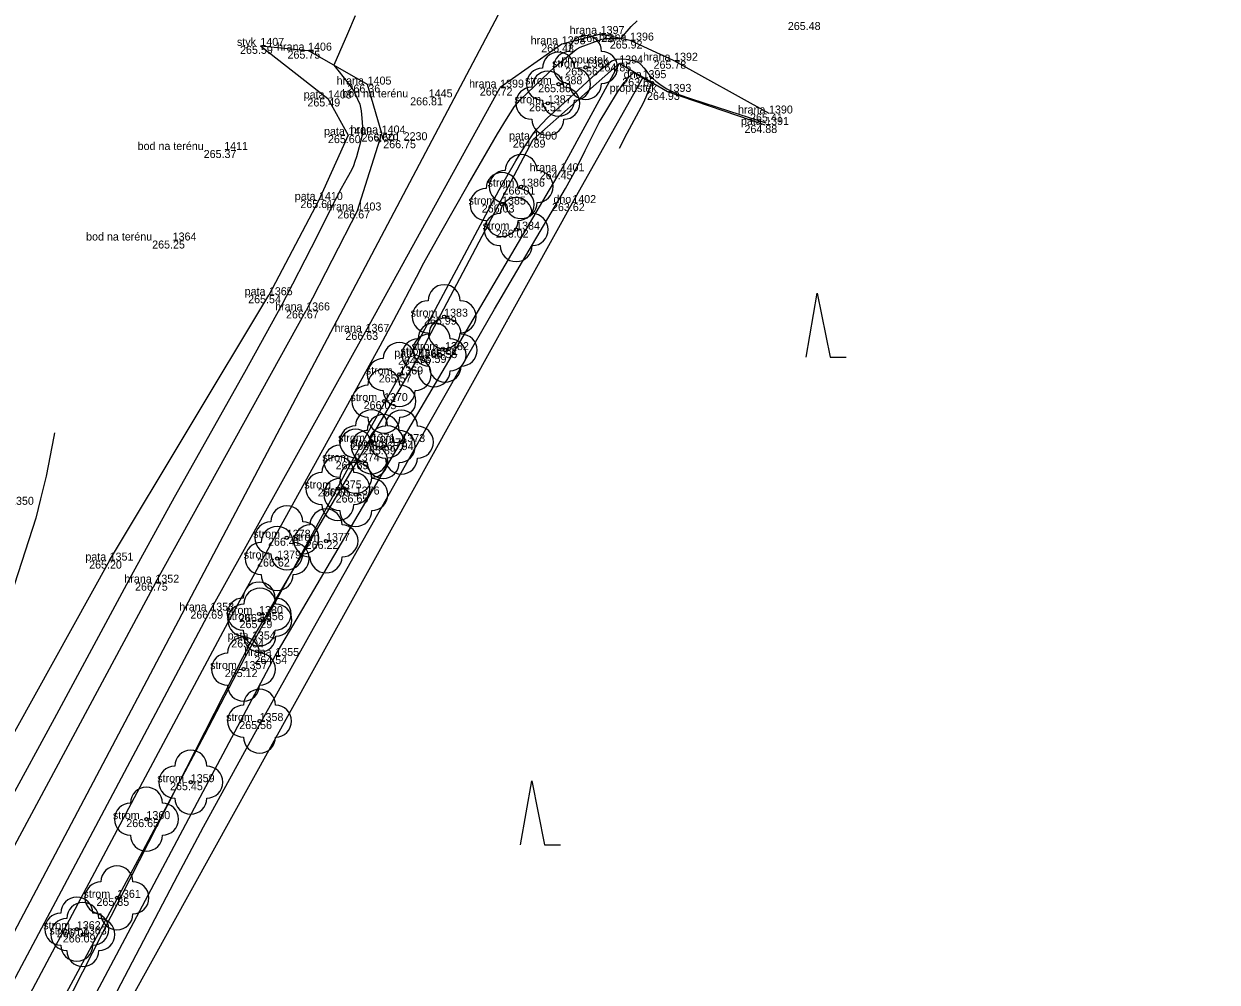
# Model space of a CAD drawing. Extents: x -567962 to -566460, y -1093720 to -1089838.
# Drawn here: x -567164.4 to -567089.8, y -1090846.6 to -1090786.7 of the extents above; entities that cross this region are included whole.
import ezdxf

# ---------------------------------------------------------------- set-up
doc = ezdxf.new("R2010")
doc.units = 0
for name, color, linetype in [('0_osa hráze', 7, 'Continuous'), ('bod_znacka', 7, 'Continuous'), ('cislo_bodu', 7, 'Continuous'), ('hlavni_vrst', 7, 'Continuous'), ('hrana_L', 7, 'Continuous'), ('hrana_P', 7, 'Continuous'), ('kod_bodu', 7, 'Continuous'), ('norm_vrst', 7, 'Continuous'), ('ostatni', 7, 'Continuous'), ('propustky', 7, 'Continuous'), ('stromy', 7, 'Continuous'), ('Vrstva 1', 7, 'Continuous'), ('vyska_bodu', 7, 'Continuous')]:
    doc.layers.add(name, color=color, linetype=linetype)

# ---------------------------------------------------------------- blocks, each defined once
blk = doc.blocks.new('3.08')
at = {"layer": 'Vrstva 1'}
blk.add_lwpolyline([(-0.07, 0), (0, 0.4), (0.08, 0), (0.18, 0)], dxfattribs=at)

msp = doc.modelspace()

# ---------------------------------------------------------------- linework, layer by layer
at = {"layer": '0_osa hráze'}
msp.add_lwpolyline([(-567089.84, -1090700.38), (-567096.414, -1090713.39), (-567177.884, -1090867.779)], dxfattribs=at)
at = {"layer": 'bod_znacka'}
for p, q in [((-567128.36, -1090787.29), (-567128.36, -1090787.29)), ((-567149.62, -1090788.03), (-567149.62, -1090788.03)), ((-567130.79, -1090787.93), (-567130.79, -1090787.93)), ((-567126.52, -1090787.7), (-567126.52, -1090787.7)), ((-567146.64, -1090788.33), (-567146.64, -1090788.33)), ((-567123.77, -1090788.96), (-567123.77, -1090788.96)), ((-567129.3, -1090789.38), (-567129.3, -1090789.38)), ((-567127.2, -1090789.13), (-567127.2, -1090789.13)), ((-567142.92, -1090790.45), (-567142.92, -1090790.45)), ((-567130.99, -1090790.43), (-567130.99, -1090790.43)), ((-567125.74, -1090790.05), (-567125.74, -1090790.05)), ((-567134.64, -1090790.64), (-567134.64, -1090790.64)), ((-567124.18, -1090790.91), (-567124.18, -1090790.91)), ((-567145.4, -1090791.32), (-567145.4, -1090791.32)), ((-567139.1, -1090791.25), (-567139.1, -1090791.25)), ((-567131.66, -1090791.62), (-567131.66, -1090791.62)), ((-567117.84, -1090792.26), (-567117.84, -1090792.26)), ((-567118.08, -1090792.98), (-567118.08, -1090792.98)), ((-567144.13, -1090793.61), (-567144.13, -1090793.61)), ((-567142.04, -1090793.51), (-567142.04, -1090793.51)), ((-567140.67, -1090793.93), (-567140.67, -1090793.93)), ((-567132.57, -1090793.89), (-567132.57, -1090793.89)), ((-567151.88, -1090794.54), (-567151.88, -1090794.54)), ((-567130.86, -1090795.87), (-567130.86, -1090795.87)), ((-567133.33, -1090796.83), (-567133.33, -1090796.83)), ((-567145.96, -1090797.67), (-567145.96, -1090797.67)), ((-567130.13, -1090797.86), (-567130.13, -1090797.86)), ((-567143.55, -1090798.32), (-567143.55, -1090798.32)), ((-567134.52, -1090797.95), (-567134.52, -1090797.95)), ((-567133.64, -1090799.52), (-567133.64, -1090799.52)), ((-567155.1, -1090800.2), (-567155.1, -1090800.2)), ((-567149.09, -1090803.62), (-567149.09, -1090803.62)), ((-567146.76, -1090804.57), (-567146.76, -1090804.57)), ((-567138.14, -1090804.96), (-567138.14, -1090804.96)), ((-567143.05, -1090805.91), (-567143.05, -1090805.91)), ((-567139.74, -1090807.47), (-567139.74, -1090807.47)), ((-567138.77, -1090807.35), (-567138.77, -1090807.35)), ((-567138.08, -1090807.05), (-567138.08, -1090807.05)), ((-567140.94, -1090808.57), (-567140.94, -1090808.57)), ((-567141.9, -1090810.24), (-567141.9, -1090810.24)), ((-567142.67, -1090812.78), (-567142.67, -1090812.78)), ((-567140.81, -1090812.8), (-567140.81, -1090812.8)), ((-567141.94, -1090813.07), (-567141.94, -1090813.07)), ((-567143.66, -1090814), (-567143.66, -1090814)), ((-567144.78, -1090815.7), (-567144.78, -1090815.7)), ((-567143.66, -1090816.08), (-567143.66, -1090816.08)), ((-567147.97, -1090818.78), (-567147.97, -1090818.78)), ((-567145.52, -1090818.98), (-567145.52, -1090818.98)), ((-567159.04, -1090820.21), (-567159.04, -1090820.21)), ((-567148.57, -1090820.08), (-567148.57, -1090820.08)), ((-567156.18, -1090821.59), (-567156.18, -1090821.59)), ((-567152.75, -1090823.34), (-567152.75, -1090823.34)), ((-567149.7, -1090823.55), (-567149.7, -1090823.55)), ((-567149.65, -1090823.93), (-567149.65, -1090823.93)), ((-567150.15, -1090825.14), (-567150.15, -1090825.14)), ((-567148.69, -1090826.17), (-567148.69, -1090826.17)), ((-567150.67, -1090826.99), (-567150.67, -1090826.99)), ((-567149.67, -1090830.24), (-567149.67, -1090830.24)), ((-567153.97, -1090834.06), (-567153.97, -1090834.06)), ((-567156.74, -1090836.37), (-567156.74, -1090836.37)), ((-567158.58, -1090841.29), (-567158.58, -1090841.29)), ((-567161.09, -1090843.25), (-567161.09, -1090843.25)), ((-567160.71, -1090843.58), (-567160.71, -1090843.58))]:
    msp.add_line(p, q, dxfattribs=at)
at = {"layer": 'hlavni_vrst'}
for points in [[(-567162.873, -1090849.36), (-567157.121, -1090838.678), (-567155.184, -1090835.033), (-567153.089, -1090831.079), (-567150.566, -1090826.245), (-567149.768, -1090824.77), (-567149.142, -1090823.648), (-567147.639, -1090820.878), (-567143.703, -1090813.646), (-567141.369, -1090809.457), (-567140.176, -1090807.295), (-567134.692, -1090797.023), (-567133.662, -1090795.222), (-567133.119, -1090794.348), (-567132.54, -1090793.478), (-567132.329, -1090793.217), (-567131.68, -1090792.532), (-567130.011, -1090791.036), (-567128.681, -1090789.807), (-567128.344, -1090789.503), (-567127.655, -1090788.976), (-567127.346, -1090788.873), (-567127.122, -1090788.845), (-567126.964, -1090788.845), (-567126.761, -1090788.859), (-567126.552, -1090788.894), (-567126.363, -1090788.938), (-567126.14, -1090789.014), (-567125.963, -1090789.098), (-567125.829, -1090789.212), (-567125.656, -1090789.396), (-567125.535, -1090789.552), (-567125.459, -1090789.669), (-567125.323, -1090789.845), (-567125.103, -1090790.068), (-567124.912, -1090790.238), (-567124.579, -1090790.487), (-567124.216, -1090790.718), (-567123.842, -1090790.904), (-567123.464, -1090791.071), (-567122.745, -1090791.326), (-567120.306, -1090792.117), (-567118.032, -1090792.837)], [(-567162.493, -1090812.221), (-567162.528, -1090812.45), (-567163.012, -1090814.932), (-567163.353, -1090816.337), (-567163.66, -1090817.553), (-567164.977, -1090821.675), (-567165.662, -1090823.624), (-567166.58, -1090826.191), (-567167.297, -1090828.123), (-567168.37, -1090830.969), (-567169.425, -1090833.739), (-567170.866, -1090837.606), (-567171.566, -1090839.547), (-567172.449, -1090842.05), (-567173.114, -1090844.011), (-567173.801, -1090846.164), (-567174.216, -1090847.494)]]:
    msp.add_lwpolyline(points, dxfattribs=at)
at = {"layer": 'hrana_L'}
for p, q in [((-567128.36, -1090787.29), (-567130.79, -1090787.93)), ((-567126.52, -1090787.7), (-567128.36, -1090787.29)), ((-567149.62, -1090788.03), (-567146.64, -1090788.33)), ((-567149.62, -1090788.03), (-567145.4, -1090791.32)), ((-567130.79, -1090787.93), (-567134.64, -1090790.64)), ((-567123.77, -1090788.96), (-567126.52, -1090787.7)), ((-567142.92, -1090790.45), (-567146.64, -1090788.33)), ((-567117.84, -1090792.26), (-567123.77, -1090788.96)), ((-567127.2, -1090789.13), (-567132.57, -1090793.89)), ((-567127.2, -1090789.13), (-567130.86, -1090795.87)), ((-567142.04, -1090793.51), (-567142.92, -1090790.45)), ((-567143.05, -1090805.91), (-567134.64, -1090790.64)), ((-567118.08, -1090792.98), (-567124.18, -1090790.91)), ((-567145.4, -1090791.32), (-567144.13, -1090793.61)), ((-567144.13, -1090793.61), (-567145.96, -1090797.67)), ((-567143.55, -1090798.32), (-567142.04, -1090793.51)), ((-567139.74, -1090807.47), (-567132.57, -1090793.89)), ((-567148.69, -1090826.17), (-567130.86, -1090795.87)), ((-567145.96, -1090797.67), (-567149.09, -1090803.62)), ((-567143.55, -1090798.32), (-567146.76, -1090804.57)), ((-567159.04, -1090820.21), (-567149.09, -1090803.62)), ((-567156.18, -1090821.59), (-567146.76, -1090804.57)), ((-567152.75, -1090823.34), (-567143.05, -1090805.91)), ((-567139.74, -1090807.47), (-567150.15, -1090825.14)), ((-567159.04, -1090820.21), (-567174.87, -1090848.67)), ((-567156.18, -1090821.59), (-567171.65, -1090850.41)), ((-567168.28, -1090852.53), (-567152.75, -1090823.34)), ((-567150.15, -1090825.14), (-567164.27, -1090852.89)), ((-567161.26, -1090849.83), (-567148.69, -1090826.17))]:
    msp.add_line(p, q, dxfattribs=at)
at = {"layer": 'hrana_P'}
for p, q in [((-567125.74, -1090790.05), (-567130.13, -1090797.86)), ((-567130.13, -1090797.86), (-567157.68, -1090847.55))]:
    msp.add_line(p, q, dxfattribs=at)
at = {"layer": 'norm_vrst'}
for points in [[(-567166.68, -1090852.281), (-567156.973, -1090834.031), (-567151.464, -1090823.75), (-567148.069, -1090817.56), (-567142.129, -1090806.774), (-567141.629, -1090805.847), (-567140.741, -1090804.164), (-567139.869, -1090802.486), (-567139.399, -1090801.596), (-567138.35, -1090799.698), (-567136.631, -1090796.701), (-567134.795, -1090793.532), (-567134.247, -1090792.613), (-567133.746, -1090791.815), (-567133.382, -1090791.403), (-567131.603, -1090789.698), (-567131.235, -1090789.367), (-567129.883, -1090788.262), (-567129.821, -1090788.221), (-567129.631, -1090788.122), (-567128.281, -1090787.61), (-567128.104, -1090787.568), (-567127.886, -1090787.562), (-567127.097, -1090787.571), (-567126.449, -1090786.829), (-567126.08, -1090786.461)], [(-567143.707, -1090786.163), (-567144.168, -1090787.289), (-567144.667, -1090788.435), (-567145.036, -1090789.244), (-567144.132, -1090790.365), (-567143.855, -1090790.747), (-567143.763, -1090790.915), (-567143.546, -1090791.363), (-567143.416, -1090791.684), (-567143.331, -1090792.091), (-567143.279, -1090792.55), (-567143.241, -1090793.092), (-567143.25, -1090793.437), (-567143.286, -1090793.695), (-567143.442, -1090794.346), (-567143.617, -1090794.962), (-567143.713, -1090795.263), (-567143.811, -1090795.531), (-567143.933, -1090795.809), (-567144.19, -1090796.28), (-567144.573, -1090796.941), (-567144.866, -1090797.5), (-567146.445, -1090800.665), (-567148, -1090803.695), (-567148.276, -1090804.217), (-567150.622, -1090808.44), (-567155.002, -1090816.274), (-567157.691, -1090821.164), (-567162.51, -1090830.095), (-567165.357, -1090835.349)], [(-567164.006, -1090857.513), (-567154.773, -1090839.877), (-567153.164, -1090836.85), (-567149.769, -1090830.667), (-567146.294, -1090824.435), (-567139.179, -1090811.796), (-567137.063, -1090808.071), (-567134.998, -1090804.501), (-567132.83, -1090800.797), (-567130.548, -1090796.938), (-567130, -1090795.922), (-567129.32, -1090794.575), (-567128.876, -1090793.655), (-567128.444, -1090792.817), (-567127.919, -1090791.917), (-567127.303, -1090790.932), (-567127.042, -1090790.532), (-567126.894, -1090790.327), (-567126.58, -1090789.959), (-567126.277, -1090789.706), (-567125.312, -1090790.273), (-567125.188, -1090790.353), (-567125.195, -1090790.399), (-567125.533, -1090791.238), (-567125.706, -1090791.608), (-567126.722, -1090793.503), (-567127.209, -1090794.449)]]:
    msp.add_lwpolyline(points, dxfattribs=at)
at = {"layer": 'propustky'}
msp.add_line((-567124.18, -1090790.91), (-567127.2, -1090789.13), dxfattribs=at)
at = {"layer": 'stromy'}
for centre in [(-567129.3, -1090789.38), (-567130.99, -1090790.43), (-567131.66, -1090791.62), (-567133.33, -1090796.83), (-567134.52, -1090797.95), (-567133.64, -1090799.52), (-567138.14, -1090804.96), (-567138.77, -1090807.35), (-567138.08, -1090807.05), (-567140.94, -1090808.57), (-567141.9, -1090810.24), (-567142.67, -1090812.78), (-567140.81, -1090812.8), (-567141.94, -1090813.07), (-567143.66, -1090814), (-567144.78, -1090815.7), (-567143.66, -1090816.08), (-567147.97, -1090818.78), (-567145.52, -1090818.98), (-567148.57, -1090820.08), (-567149.7, -1090823.55), (-567149.65, -1090823.93), (-567150.67, -1090826.99), (-567149.67, -1090830.24), (-567153.97, -1090834.06), (-567156.74, -1090836.37), (-567158.58, -1090841.29), (-567161.09, -1090843.25), (-567160.71, -1090843.58)]:
    msp.add_circle(centre, 0.1, dxfattribs=at)
for centre, start, end in [((-567129.3, -1090788.38), 0, 180), ((-567130.99, -1090789.43), 0, 180), ((-567130.3, -1090789.38), 90, 270), ((-567128.3, -1090789.38), 270, 90), ((-567131.99, -1090790.43), 90, 270), ((-567131.66, -1090790.62), 0, 180), ((-567129.99, -1090790.43), 270, 90), ((-567129.3, -1090790.38), 180, 0), ((-567132.66, -1090791.62), 90, 270), ((-567130.66, -1090791.62), 270, 90), ((-567130.99, -1090791.43), 180, 0), ((-567131.66, -1090792.62), 180, 0), ((-567133.33, -1090795.83), 0, 180), ((-567134.52, -1090796.95), 0, 180), ((-567134.33, -1090796.83), 90, 270), ((-567132.33, -1090796.83), 270, 90), ((-567135.52, -1090797.95), 90, 270), ((-567133.52, -1090797.95), 270, 90), ((-567133.64, -1090798.52), 0, 180), ((-567133.33, -1090797.83), 180, 0), ((-567134.64, -1090799.52), 90, 270), ((-567132.64, -1090799.52), 270, 90), ((-567134.52, -1090798.95), 180, 0), ((-567133.64, -1090800.52), 180, 0), ((-567138.14, -1090803.96), 0, 180), ((-567139.14, -1090804.96), 90, 270), ((-567137.14, -1090804.96), 270, 90), ((-567138.77, -1090806.35), 0, 180), ((-567138.08, -1090806.05), 0, 180), ((-567139.08, -1090807.05), 90, 270), ((-567138.14, -1090805.96), 180, 0), ((-567137.08, -1090807.05), 270, 90), ((-567140.94, -1090807.57), 0, 180), ((-567139.77, -1090807.35), 90, 270), ((-567137.77, -1090807.35), 270, 90), ((-567141.94, -1090808.57), 90, 270), ((-567139.94, -1090808.57), 270, 90), ((-567141.9, -1090809.24), 0, 180), ((-567138.77, -1090808.35), 180, 0), ((-567138.08, -1090808.05), 180, 0), ((-567142.9, -1090810.24), 90, 270), ((-567140.94, -1090809.57), 180, 0), ((-567140.9, -1090810.24), 270, 90), ((-567142.67, -1090811.78), 0, 180), ((-567141.94, -1090812.07), 0, 180), ((-567141.9, -1090811.24), 180, 0), ((-567140.81, -1090811.8), 0, 180), ((-567143.67, -1090812.78), 90, 270), ((-567143.66, -1090813), 0, 180), ((-567142.94, -1090813.07), 90, 270), ((-567141.81, -1090812.8), 90, 270), ((-567141.67, -1090812.78), 270, 90), ((-567140.94, -1090813.07), 270, 90), ((-567139.81, -1090812.8), 270, 90), ((-567144.66, -1090814), 90, 270), ((-567142.66, -1090814), 270, 90), ((-567144.78, -1090814.7), 0, 180), ((-567143.66, -1090815.08), 0, 180), ((-567142.67, -1090813.78), 180, 0), ((-567141.94, -1090814.07), 180, 0), ((-567140.81, -1090813.8), 180, 0), ((-567145.78, -1090815.7), 90, 270), ((-567143.66, -1090815), 180, 0), ((-567143.78, -1090815.7), 270, 90), ((-567144.66, -1090816.08), 90, 270), ((-567142.66, -1090816.08), 270, 90), ((-567147.97, -1090817.78), 0, 180), ((-567145.52, -1090817.98), 0, 180), ((-567144.78, -1090816.7), 180, 0), ((-567143.66, -1090817.08), 180, 0), ((-567148.97, -1090818.78), 90, 270), ((-567146.52, -1090818.98), 90, 270), ((-567146.97, -1090818.78), 270, 90), ((-567144.52, -1090818.98), 270, 90), ((-567148.57, -1090819.08), 0, 180), ((-567149.57, -1090820.08), 90, 270), ((-567147.57, -1090820.08), 270, 90), ((-567147.97, -1090819.78), 180, 0), ((-567145.52, -1090819.98), 180, 0), ((-567149.7, -1090822.55), 0, 180), ((-567148.57, -1090821.08), 180, 0), ((-567149.65, -1090822.93), 0, 180), ((-567150.7, -1090823.55), 90, 270), ((-567150.65, -1090823.93), 90, 270), ((-567148.7, -1090823.55), 270, 90), ((-567148.65, -1090823.93), 270, 90), ((-567149.7, -1090824.55), 180, 0), ((-567150.67, -1090825.99), 0, 180), ((-567149.65, -1090824.93), 180, 0), ((-567151.67, -1090826.99), 90, 270), ((-567149.67, -1090826.99), 270, 90), ((-567150.67, -1090827.99), 180, 0), ((-567149.67, -1090829.24), 0, 180), ((-567150.67, -1090830.24), 90, 270), ((-567148.67, -1090830.24), 270, 90), ((-567149.67, -1090831.24), 180, 0), ((-567153.97, -1090833.06), 0, 180), ((-567154.97, -1090834.06), 90, 270), ((-567152.97, -1090834.06), 270, 90), ((-567156.74, -1090835.37), 0, 180), ((-567153.97, -1090835.06), 180, 0), ((-567157.74, -1090836.37), 90, 270), ((-567155.74, -1090836.37), 270, 90), ((-567156.74, -1090837.37), 180, 0), ((-567158.58, -1090840.29), 0, 180), ((-567159.58, -1090841.29), 90, 270), ((-567157.58, -1090841.29), 270, 90), ((-567161.09, -1090842.25), 0, 180), ((-567160.71, -1090842.58), 0, 180), ((-567162.09, -1090843.25), 90, 270), ((-567161.71, -1090843.58), 90, 270), ((-567160.09, -1090843.25), 270, 90), ((-567159.71, -1090843.58), 270, 90), ((-567158.58, -1090842.29), 180, 0), ((-567161.09, -1090844.25), 180, 0), ((-567160.71, -1090844.58), 180, 0)]:
    msp.add_arc(centre, 1, start, end, dxfattribs=at)

# ---------------------------------------------------------------- block references
at = {"layer": 'ostatni', "xscale": 10, "yscale": 10}
for p in [(-567114.822, -1090807.496), (-567132.668, -1090837.974)]:
    msp.add_blockref('3.08', p, dxfattribs=at)

# ---------------------------------------------------------------- texts
at = {"layer": 'cislo_bodu'}
for s, p in [('1398', (-567130.79, -1090787.93)), ('1397', (-567128.36, -1090787.29)), ('1396', (-567126.52, -1090787.7)), ('1407', (-567149.62, -1090788.03)), ('1406', (-567146.64, -1090788.33)), ('1389', (-567129.3, -1090789.38)), ('1394', (-567127.2, -1090789.13)), ('1392', (-567123.77, -1090788.96)), ('1395', (-567125.74, -1090790.05)), ('1405', (-567142.92, -1090790.45)), ('1399', (-567134.64, -1090790.64)), ('1388', (-567130.99, -1090790.43)), ('1393', (-567124.18, -1090790.91)), ('1408', (-567145.4, -1090791.32)), ('1445', (-567139.1, -1090791.25)), ('1387', (-567131.66, -1090791.62)), ('1390', (-567117.84, -1090792.26)), ('1391', (-567118.08, -1090792.98)), ('1409', (-567144.13, -1090793.61)), ('1404', (-567142.04, -1090793.51)), ('2230', (-567140.67, -1090793.93)), ('1400', (-567132.57, -1090793.89)), ('1411', (-567151.88, -1090794.54)), ('1401', (-567130.86, -1090795.87)), ('1386', (-567133.33, -1090796.83)), ('1410', (-567145.96, -1090797.67)), ('1403', (-567143.55, -1090798.32)), ('1385', (-567134.52, -1090797.95)), ('1402', (-567130.13, -1090797.86)), ('1384', (-567133.64, -1090799.52)), ('1364', (-567155.1, -1090800.2)), ('1365', (-567149.09, -1090803.62)), ('1366', (-567146.76, -1090804.57)), ('1383', (-567138.14, -1090804.96)), ('1367', (-567143.05, -1090805.91)), ('1381', (-567138.77, -1090807.35)), ('1382', (-567138.08, -1090807.05)), ('1368', (-567139.74, -1090807.47)), ('1369', (-567140.94, -1090808.57)), ('1370', (-567141.9, -1090810.24)), ('1371', (-567142.67, -1090812.78)), ('1372', (-567141.94, -1090813.07)), ('1373', (-567140.81, -1090812.8)), ('1374', (-567143.66, -1090814)), ('1375', (-567144.78, -1090815.7)), ('1376', (-567143.66, -1090816.08)), ('1350', (-567165.26, -1090816.72)), ('1378', (-567147.97, -1090818.78)), ('1377', (-567145.52, -1090818.98)), ('1351', (-567159.04, -1090820.21)), ('1379', (-567148.57, -1090820.08)), ('1352', (-567156.18, -1090821.59)), ('1353', (-567152.75, -1090823.34)), ('1380', (-567149.7, -1090823.55)), ('1356', (-567149.65, -1090823.93)), ('1354', (-567150.15, -1090825.14)), ('1355', (-567148.69, -1090826.17)), ('1357', (-567150.67, -1090826.99)), ('1358', (-567149.67, -1090830.24)), ('1359', (-567153.97, -1090834.06)), ('1360', (-567156.74, -1090836.37)), ('1361', (-567158.58, -1090841.29)), ('1362', (-567161.09, -1090843.25)), ('1363', (-567160.71, -1090843.58))]:
    msp.add_text(s, height=0.5, dxfattribs=at).set_placement(p)
at = {"layer": 'kod_bodu'}
for s, p in [('hrana', (-567132.727, -1090787.93)), ('hrana', (-567130.297, -1090787.29)), ('hrana', (-567128.457, -1090787.7)), ('styk', (-567151.084, -1090788.03)), ('hrana', (-567148.577, -1090788.33)), ('strom', (-567131.394, -1090789.38)), ('propustek', (-567130.814, -1090789.13)), ('hrana', (-567125.707, -1090788.96)), ('dno', (-567126.921, -1090790.05)), ('hrana', (-567144.857, -1090790.45)), ('hrana', (-567136.577, -1090790.64)), ('strom', (-567133.084, -1090790.43)), ('propustek', (-567127.794, -1090790.91)), ('pata', (-567146.912, -1090791.32)), ('bod na terénu', (-567144.509, -1090791.25)), ('strom', (-567133.754, -1090791.62)), ('hrana', (-567119.777, -1090792.26)), ('pata', (-567119.592, -1090792.98)), ('pata', (-567145.642, -1090793.61)), ('hrana', (-567143.977, -1090793.51)), ('sjezd', (-567142.536, -1090793.93)), ('pata', (-567134.082, -1090793.89)), ('bod na terénu', (-567157.289, -1090794.54)), ('hrana', (-567132.797, -1090795.87)), ('strom', (-567135.424, -1090796.83)), ('pata', (-567147.472, -1090797.67)), ('hrana', (-567145.487, -1090798.32)), ('strom', (-567136.614, -1090797.95)), ('dno', (-567131.311, -1090797.86)), ('strom', (-567135.734, -1090799.52)), ('bod na terénu', (-567160.509, -1090800.2)), ('pata', (-567150.602, -1090803.62)), ('hrana', (-567148.697, -1090804.57)), ('strom', (-567140.234, -1090804.96)), ('hrana', (-567144.987, -1090805.91)), ('strom', (-567140.174, -1090807.05)), ('pata', (-567141.252, -1090807.47)), ('strom', (-567140.864, -1090807.35)), ('strom', (-567143.034, -1090808.57)), ('strom', (-567143.994, -1090810.24)), ('strom', (-567144.764, -1090812.78)), ('strom', (-567144.034, -1090813.07)), ('strom', (-567142.904, -1090812.8)), ('strom', (-567145.754, -1090814)), ('strom', (-567146.874, -1090815.7)), ('strom', (-567145.754, -1090816.08)), ('strom', (-567150.064, -1090818.78)), ('strom', (-567147.614, -1090818.98)), ('pata', (-567160.552, -1090820.21)), ('strom', (-567150.664, -1090820.08)), ('hrana', (-567158.117, -1090821.59)), ('hrana', (-567154.687, -1090823.34)), ('strom', (-567151.794, -1090823.55)), ('strom', (-567151.744, -1090823.93)), ('pata', (-567151.662, -1090825.14)), ('hrana', (-567150.627, -1090826.17)), ('strom', (-567152.764, -1090826.99)), ('strom', (-567151.764, -1090830.24)), ('strom', (-567156.064, -1090834.06)), ('strom', (-567158.834, -1090836.37)), ('strom', (-567160.674, -1090841.29)), ('strom', (-567163.184, -1090843.25)), ('strom', (-567162.804, -1090843.58))]:
    msp.add_text(s, height=0.5, dxfattribs=at).set_placement(p)
at = {"layer": 'vyska_bodu'}
for s, p in [('265.48', (-567116.663, -1090787.04)), ('266.22', (-567129.63, -1090787.79)), ('265.59', (-567150.89, -1090788.53)), ('266.43', (-567132.071, -1090788.43)), ('265.92', (-567127.79, -1090788.2)), ('265.75', (-567147.923, -1090788.83)), ('265.78', (-567125.053, -1090789.46)), ('265.56', (-567130.57, -1090789.88)), ('264.85', (-567128.493, -1090789.63)), ('266.36', (-567144.178, -1090790.95)), ('265.86', (-567132.26, -1090790.93)), ('263.65', (-567127.01, -1090790.55)), ('266.72', (-567135.912, -1090791.14)), ('264.93', (-567125.461, -1090791.41)), ('265.49', (-567146.681, -1090791.82)), ('266.81', (-567140.261, -1090791.75)), ('265.51', (-567132.833, -1090792.12)), ('265.41', (-567119.025, -1090792.76)), ('264.88', (-567119.373, -1090793.48)), ('265.60', (-567145.398, -1090794.11)), ('266.60', (-567143.296, -1090794.01)), ('266.75', (-567141.942, -1090794.43)), ('264.89', (-567133.851, -1090794.39)), ('265.37', (-567153.163, -1090795.04)), ('264.45', (-567132.165, -1090796.37)), ('266.01', (-567134.489, -1090797.33)), ('265.61', (-567147.121, -1090798.17)), ('263.62', (-567131.4, -1090798.36)), ('266.67', (-567144.81, -1090798.82)), ('266.03', (-567135.788, -1090798.45)), ('266.02', (-567134.908, -1090800.02)), ('265.25', (-567156.381, -1090800.7)), ('265.54', (-567150.383, -1090804.12)), ('266.67', (-567148.02, -1090805.07)), ('265.99', (-567139.398, -1090805.46)), ('266.63', (-567144.308, -1090806.41)), ('264.76', (-567141.023, -1090807.97)), ('265.59', (-567140.04, -1090807.85)), ('265.55', (-567139.361, -1090807.55)), ('265.57', (-567142.223, -1090809.07)), ('266.05', (-567143.168, -1090810.74)), ('265.89', (-567143.94, -1090813.28)), ('265.94', (-567142.091, -1090813.3)), ('265.89', (-567143.21, -1090813.57)), ('265.69', (-567144.918, -1090814.5)), ('266.65', (-567146.038, -1090816.2)), ('266.65', (-567144.918, -1090816.58)), ('266.41', (-567149.143, -1090819.28)), ('266.22', (-567146.79, -1090819.48)), ('265.20', (-567160.319, -1090820.71)), ('266.62', (-567149.828, -1090820.58)), ('266.75', (-567157.452, -1090822.09)), ('266.69', (-567153.996, -1090823.84)), ('266.59', (-567150.958, -1090824.05)), ('265.29', (-567150.92, -1090824.43)), ('265.04', (-567151.441, -1090825.64)), ('264.54', (-567149.995, -1090826.67)), ('265.12', (-567151.843, -1090827.49)), ('265.56', (-567150.94, -1090830.74)), ('265.45', (-567155.263, -1090834.56)), ('266.65', (-567157.998, -1090836.87)), ('265.85', (-567159.861, -1090841.79)), ('266.09', (-567162.346, -1090843.75)), ('266.09', (-567161.966, -1090844.08))]:
    msp.add_text(s, height=0.5, dxfattribs=at).set_placement(p)

doc.saveas('drawing.dxf')
